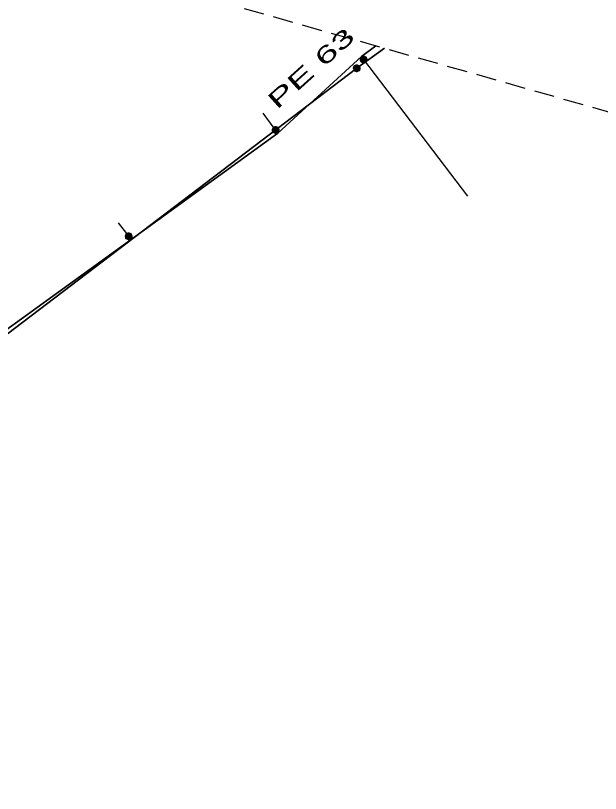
# Model space of a CAD drawing. Extents: x -873619 to -867639, y -1015082 to -1012326.
# Drawn here: x -868054.5 to -868016.1, y -1012689.5 to -1012638.4 of the extents above; entities that cross this region are included whole.
import ezdxf

# ---------------------------------------------------------------- set-up
doc = ezdxf.new("R2010")
doc.units = 0
doc.header["$LTSCALE"] = 0.44
doc.linetypes.add('MEDIUM_DASHED', pattern=[4.5, 3, -1.5])
for name, color, linetype, lineweight in [('1', 7, 'Continuous', 13), ('12', 7, 'Continuous', 13), ('21', 7, 'Continuous', 35), ('25', 7, 'Continuous', 13), ('3', 7, 'Continuous', 25), ('62', 7, 'MEDIUM_DASHED', 25)]:
    doc.layers.add(name, color=color, linetype=linetype, lineweight=lineweight)

msp = doc.modelspace()

# ---------------------------------------------------------------- linework, layer by layer
at = {"layer": '1', "lineweight": 35}
msp.add_lwpolyline([(-868030.886, -1012640.414), (-868031.841, -1012641.12), (-868037.319, -1012646.139), (-868046.957, -1012653.118), (-868059.317, -1012662.058), (-868070.578, -1012671.039), (-868077.42, -1012675.76), (-868086.156, -1012682.341)], dxfattribs=at)
at = {"layer": '12'}
for points in [[(-868031.458, -1012641.32), (-868031.465, -1012641.268), (-868031.482, -1012641.218), (-868031.511, -1012641.174), (-868031.548, -1012641.137), (-868031.593, -1012641.11), (-868031.642, -1012641.093), (-868031.696, -1012641.089), (-868031.747, -1012641.096), (-868031.796, -1012641.115), (-868031.84, -1012641.144), (-868031.875, -1012641.183), (-868031.902, -1012641.228), (-868031.918, -1012641.279), (-868031.921, -1012641.331), (-868031.913, -1012641.383), (-868031.892, -1012641.432), (-868031.862, -1012641.475), (-868031.823, -1012641.509), (-868031.777, -1012641.535), (-868031.725, -1012641.549), (-868031.673, -1012641.551), (-868031.622, -1012641.541), (-868031.573, -1012641.52), (-868031.531, -1012641.489), (-868031.497, -1012641.448), (-868031.473, -1012641.402), (-868031.46, -1012641.351)], [(-868031.489, -1012641.32), (-868031.495, -1012641.271), (-868031.512, -1012641.225), (-868031.539, -1012641.185), (-868031.576, -1012641.153), (-868031.62, -1012641.131), (-868031.669, -1012641.12), (-868031.718, -1012641.12), (-868031.764, -1012641.133), (-868031.808, -1012641.157), (-868031.843, -1012641.19), (-868031.87, -1012641.231), (-868031.887, -1012641.278), (-868031.891, -1012641.327), (-868031.884, -1012641.375), (-868031.865, -1012641.42), (-868031.835, -1012641.46), (-868031.796, -1012641.491), (-868031.752, -1012641.511), (-868031.705, -1012641.521), (-868031.656, -1012641.519), (-868031.608, -1012641.504), (-868031.566, -1012641.479), (-868031.531, -1012641.445), (-868031.505, -1012641.403), (-868031.492, -1012641.356)], [(-868031.519, -1012641.32), (-868031.524, -1012641.275), (-868031.541, -1012641.233), (-868031.57, -1012641.198), (-868031.605, -1012641.171), (-868031.647, -1012641.154), (-868031.693, -1012641.149), (-868031.737, -1012641.155), (-868031.779, -1012641.174), (-868031.813, -1012641.202), (-868031.84, -1012641.239), (-868031.857, -1012641.281), (-868031.86, -1012641.326), (-868031.853, -1012641.371), (-868031.835, -1012641.412), (-868031.806, -1012641.446), (-868031.769, -1012641.472), (-868031.725, -1012641.488), (-868031.681, -1012641.491), (-868031.636, -1012641.483), (-868031.595, -1012641.463), (-868031.561, -1012641.434), (-868031.536, -1012641.396), (-868031.522, -1012641.353)], [(-868031.549, -1012641.32), (-868031.553, -1012641.279), (-868031.571, -1012641.242), (-868031.598, -1012641.211), (-868031.634, -1012641.19), (-868031.674, -1012641.179), (-868031.715, -1012641.181), (-868031.754, -1012641.194), (-868031.788, -1012641.218), (-868031.813, -1012641.25), (-868031.828, -1012641.288), (-868031.83, -1012641.329), (-868031.823, -1012641.369), (-868031.803, -1012641.405), (-868031.774, -1012641.434), (-868031.737, -1012641.453), (-868031.696, -1012641.461), (-868031.656, -1012641.457), (-868031.617, -1012641.442), (-868031.585, -1012641.416), (-868031.563, -1012641.382), (-868031.549, -1012641.343)], [(-868031.578, -1012641.32), (-868031.583, -1012641.284), (-868031.602, -1012641.252), (-868031.627, -1012641.227), (-868031.661, -1012641.212), (-868031.698, -1012641.209), (-868031.732, -1012641.217), (-868031.764, -1012641.237), (-868031.786, -1012641.265), (-868031.799, -1012641.299), (-868031.799, -1012641.336), (-868031.789, -1012641.371), (-868031.767, -1012641.4), (-868031.737, -1012641.421), (-868031.703, -1012641.431), (-868031.666, -1012641.429), (-868031.632, -1012641.415), (-868031.605, -1012641.392), (-868031.585, -1012641.36), (-868031.578, -1012641.325)], [(-868031.608, -1012641.32), (-868031.614, -1012641.289), (-868031.63, -1012641.263), (-868031.656, -1012641.246), (-868031.686, -1012641.239), (-868031.718, -1012641.243), (-868031.745, -1012641.26), (-868031.762, -1012641.284), (-868031.771, -1012641.315), (-868031.767, -1012641.345), (-868031.752, -1012641.373), (-868031.727, -1012641.392), (-868031.698, -1012641.401), (-868031.666, -1012641.398), (-868031.639, -1012641.384), (-868031.619, -1012641.36), (-868031.608, -1012641.331)], [(-868031.639, -1012641.32), (-868031.644, -1012641.296), (-868031.661, -1012641.278), (-868031.683, -1012641.269), (-868031.708, -1012641.272), (-868031.728, -1012641.286), (-868031.74, -1012641.308), (-868031.74, -1012641.333), (-868031.727, -1012641.354), (-868031.708, -1012641.368), (-868031.683, -1012641.371), (-868031.659, -1012641.362), (-868031.644, -1012641.344)], [(-868031.669, -1012641.32), (-868031.674, -1012641.305), (-868031.688, -1012641.299), (-868031.703, -1012641.303), (-868031.71, -1012641.317), (-868031.706, -1012641.332), (-868031.693, -1012641.341), (-868031.678, -1012641.338), (-868031.669, -1012641.326)], [(-868037.238, -1012645.94), (-868037.244, -1012645.888), (-868037.261, -1012645.838), (-868037.29, -1012645.794), (-868037.327, -1012645.757), (-868037.372, -1012645.73), (-868037.422, -1012645.713), (-868037.475, -1012645.709), (-868037.527, -1012645.716), (-868037.576, -1012645.735), (-868037.619, -1012645.764), (-868037.655, -1012645.803), (-868037.681, -1012645.848), (-868037.697, -1012645.899), (-868037.7, -1012645.951), (-868037.692, -1012646.003), (-868037.672, -1012646.052), (-868037.641, -1012646.095), (-868037.602, -1012646.129), (-868037.556, -1012646.155), (-868037.505, -1012646.169), (-868037.452, -1012646.171), (-868037.401, -1012646.161), (-868037.353, -1012646.14), (-868037.31, -1012646.109), (-868037.276, -1012646.068), (-868037.252, -1012646.022), (-868037.24, -1012645.971)], [(-868037.268, -1012645.94), (-868037.274, -1012645.891), (-868037.291, -1012645.845), (-868037.319, -1012645.805), (-868037.356, -1012645.773), (-868037.4, -1012645.751), (-868037.448, -1012645.74), (-868037.497, -1012645.74), (-868037.544, -1012645.753), (-868037.587, -1012645.777), (-868037.623, -1012645.81), (-868037.65, -1012645.851), (-868037.666, -1012645.898), (-868037.67, -1012645.947), (-868037.663, -1012645.995), (-868037.644, -1012646.04), (-868037.614, -1012646.08), (-868037.576, -1012646.111), (-868037.532, -1012646.131), (-868037.484, -1012646.141), (-868037.435, -1012646.139), (-868037.388, -1012646.124), (-868037.345, -1012646.099), (-868037.311, -1012646.065), (-868037.285, -1012646.023), (-868037.271, -1012645.976)], [(-868037.298, -1012645.94), (-868037.304, -1012645.895), (-868037.321, -1012645.853), (-868037.349, -1012645.818), (-868037.385, -1012645.791), (-868037.427, -1012645.774), (-868037.472, -1012645.769), (-868037.517, -1012645.775), (-868037.558, -1012645.794), (-868037.593, -1012645.822), (-868037.62, -1012645.859), (-868037.636, -1012645.901), (-868037.64, -1012645.946), (-868037.633, -1012645.991), (-868037.614, -1012646.032), (-868037.585, -1012646.066), (-868037.548, -1012646.092), (-868037.505, -1012646.108), (-868037.46, -1012646.111), (-868037.415, -1012646.103), (-868037.375, -1012646.083), (-868037.341, -1012646.054), (-868037.315, -1012646.016), (-868037.301, -1012645.973)], [(-868037.328, -1012645.94), (-868037.333, -1012645.899), (-868037.351, -1012645.862), (-868037.378, -1012645.831), (-868037.413, -1012645.81), (-868037.453, -1012645.799), (-868037.494, -1012645.801), (-868037.533, -1012645.814), (-868037.567, -1012645.838), (-868037.592, -1012645.87), (-868037.607, -1012645.908), (-868037.61, -1012645.949), (-868037.602, -1012645.989), (-868037.582, -1012646.025), (-868037.553, -1012646.054), (-868037.516, -1012646.073), (-868037.476, -1012646.081), (-868037.435, -1012646.077), (-868037.397, -1012646.062), (-868037.365, -1012646.036), (-868037.342, -1012646.002), (-868037.329, -1012645.963)], [(-868037.358, -1012645.94), (-868037.363, -1012645.904), (-868037.381, -1012645.872), (-868037.407, -1012645.847), (-868037.441, -1012645.832), (-868037.477, -1012645.829), (-868037.512, -1012645.837), (-868037.543, -1012645.857), (-868037.566, -1012645.885), (-868037.579, -1012645.919), (-868037.579, -1012645.956), (-868037.568, -1012645.991), (-868037.547, -1012646.02), (-868037.517, -1012646.041), (-868037.482, -1012646.051), (-868037.445, -1012646.049), (-868037.411, -1012646.035), (-868037.384, -1012646.012), (-868037.365, -1012645.98), (-868037.358, -1012645.945)], [(-868037.388, -1012645.94), (-868037.393, -1012645.909), (-868037.41, -1012645.883), (-868037.436, -1012645.866), (-868037.466, -1012645.859), (-868037.497, -1012645.863), (-868037.524, -1012645.88), (-868037.542, -1012645.904), (-868037.55, -1012645.935), (-868037.546, -1012645.965), (-868037.531, -1012645.993), (-868037.507, -1012646.012), (-868037.477, -1012646.021), (-868037.446, -1012646.018), (-868037.418, -1012646.004), (-868037.398, -1012645.98), (-868037.388, -1012645.951)], [(-868037.418, -1012645.94), (-868037.423, -1012645.916), (-868037.44, -1012645.898), (-868037.463, -1012645.889), (-868037.487, -1012645.892), (-868037.508, -1012645.906), (-868037.519, -1012645.928), (-868037.519, -1012645.953), (-868037.507, -1012645.974), (-868037.487, -1012645.988), (-868037.462, -1012645.991), (-868037.439, -1012645.982), (-868037.423, -1012645.964)], [(-868037.448, -1012645.94), (-868037.453, -1012645.925), (-868037.468, -1012645.919), (-868037.483, -1012645.923), (-868037.49, -1012645.937), (-868037.486, -1012645.952), (-868037.473, -1012645.961), (-868037.458, -1012645.958), (-868037.448, -1012645.946)], [(-868046.878, -1012652.918), (-868046.884, -1012652.866), (-868046.901, -1012652.816), (-868046.93, -1012652.772), (-868046.967, -1012652.735), (-868047.012, -1012652.708), (-868047.062, -1012652.691), (-868047.115, -1012652.687), (-868047.167, -1012652.694), (-868047.216, -1012652.713), (-868047.259, -1012652.742), (-868047.295, -1012652.781), (-868047.321, -1012652.826), (-868047.337, -1012652.877), (-868047.34, -1012652.929), (-868047.332, -1012652.981), (-868047.312, -1012653.03), (-868047.281, -1012653.073), (-868047.242, -1012653.107), (-868047.196, -1012653.133), (-868047.145, -1012653.147), (-868047.092, -1012653.149), (-868047.041, -1012653.139), (-868046.993, -1012653.118), (-868046.95, -1012653.087), (-868046.916, -1012653.046), (-868046.892, -1012653), (-868046.88, -1012652.949)], [(-868046.908, -1012652.918), (-868046.914, -1012652.869), (-868046.931, -1012652.823), (-868046.959, -1012652.783), (-868046.996, -1012652.751), (-868047.04, -1012652.729), (-868047.088, -1012652.718), (-868047.137, -1012652.718), (-868047.184, -1012652.731), (-868047.227, -1012652.755), (-868047.263, -1012652.788), (-868047.29, -1012652.829), (-868047.306, -1012652.876), (-868047.31, -1012652.925), (-868047.303, -1012652.973), (-868047.284, -1012653.018), (-868047.254, -1012653.058), (-868047.216, -1012653.089), (-868047.172, -1012653.109), (-868047.124, -1012653.119), (-868047.075, -1012653.117), (-868047.028, -1012653.102), (-868046.985, -1012653.077), (-868046.951, -1012653.043), (-868046.925, -1012653.001), (-868046.911, -1012652.954)], [(-868046.938, -1012652.918), (-868046.944, -1012652.873), (-868046.961, -1012652.831), (-868046.989, -1012652.796), (-868047.025, -1012652.769), (-868047.067, -1012652.752), (-868047.112, -1012652.747), (-868047.157, -1012652.753), (-868047.198, -1012652.772), (-868047.233, -1012652.8), (-868047.26, -1012652.837), (-868047.276, -1012652.879), (-868047.28, -1012652.924), (-868047.273, -1012652.969), (-868047.254, -1012653.01), (-868047.225, -1012653.044), (-868047.188, -1012653.07), (-868047.145, -1012653.086), (-868047.1, -1012653.089), (-868047.055, -1012653.081), (-868047.015, -1012653.061), (-868046.981, -1012653.032), (-868046.955, -1012652.994), (-868046.941, -1012652.951)], [(-868046.968, -1012652.918), (-868046.973, -1012652.877), (-868046.991, -1012652.84), (-868047.018, -1012652.809), (-868047.053, -1012652.788), (-868047.093, -1012652.777), (-868047.134, -1012652.779), (-868047.173, -1012652.792), (-868047.207, -1012652.816), (-868047.232, -1012652.848), (-868047.247, -1012652.886), (-868047.25, -1012652.927), (-868047.242, -1012652.967), (-868047.222, -1012653.003), (-868047.193, -1012653.032), (-868047.156, -1012653.051), (-868047.116, -1012653.059), (-868047.075, -1012653.055), (-868047.037, -1012653.04), (-868047.005, -1012653.014), (-868046.982, -1012652.98), (-868046.969, -1012652.941)], [(-868046.998, -1012652.918), (-868047.003, -1012652.882), (-868047.021, -1012652.85), (-868047.047, -1012652.825), (-868047.081, -1012652.81), (-868047.117, -1012652.807), (-868047.152, -1012652.815), (-868047.183, -1012652.835), (-868047.206, -1012652.863), (-868047.219, -1012652.897), (-868047.219, -1012652.934), (-868047.208, -1012652.969), (-868047.187, -1012652.998), (-868047.157, -1012653.019), (-868047.122, -1012653.029), (-868047.085, -1012653.027), (-868047.051, -1012653.013), (-868047.024, -1012652.99), (-868047.005, -1012652.958), (-868046.998, -1012652.923)], [(-868047.028, -1012652.918), (-868047.033, -1012652.887), (-868047.05, -1012652.861), (-868047.076, -1012652.844), (-868047.106, -1012652.837), (-868047.137, -1012652.841), (-868047.164, -1012652.858), (-868047.182, -1012652.882), (-868047.19, -1012652.913), (-868047.186, -1012652.943), (-868047.171, -1012652.971), (-868047.147, -1012652.99), (-868047.117, -1012652.999), (-868047.086, -1012652.996), (-868047.058, -1012652.982), (-868047.038, -1012652.958), (-868047.028, -1012652.929)], [(-868047.058, -1012652.918), (-868047.063, -1012652.894), (-868047.08, -1012652.876), (-868047.103, -1012652.867), (-868047.127, -1012652.87), (-868047.148, -1012652.884), (-868047.159, -1012652.906), (-868047.159, -1012652.931), (-868047.147, -1012652.952), (-868047.127, -1012652.966), (-868047.102, -1012652.969), (-868047.079, -1012652.96), (-868047.063, -1012652.942)], [(-868047.088, -1012652.918), (-868047.093, -1012652.903), (-868047.108, -1012652.897), (-868047.123, -1012652.901), (-868047.13, -1012652.915), (-868047.126, -1012652.93), (-868047.113, -1012652.939), (-868047.098, -1012652.936), (-868047.088, -1012652.924)]]:
    msp.add_lwpolyline(points, close=True, dxfattribs=at)
at = {"layer": '21'}
msp.add_lwpolyline([(-868071.05, -1012671.53), (-868057.2, -1012660.92), (-868032.14, -1012641.89), (-868030.331, -1012640.572)], dxfattribs=at)
at = {"layer": '25'}
for points in [[(-868031.909, -1012641.89), (-868031.915, -1012641.838), (-868031.932, -1012641.788), (-868031.961, -1012641.744), (-868031.998, -1012641.707), (-868032.043, -1012641.68), (-868032.093, -1012641.663), (-868032.146, -1012641.659), (-868032.198, -1012641.666), (-868032.247, -1012641.685), (-868032.29, -1012641.714), (-868032.326, -1012641.753), (-868032.352, -1012641.798), (-868032.368, -1012641.849), (-868032.371, -1012641.901), (-868032.363, -1012641.953), (-868032.343, -1012642.002), (-868032.312, -1012642.045), (-868032.273, -1012642.079), (-868032.227, -1012642.105), (-868032.176, -1012642.119), (-868032.123, -1012642.121), (-868032.072, -1012642.111), (-868032.024, -1012642.09), (-868031.981, -1012642.059), (-868031.947, -1012642.018), (-868031.923, -1012641.972), (-868031.911, -1012641.921)], [(-868031.939, -1012641.89), (-868031.945, -1012641.841), (-868031.962, -1012641.795), (-868031.99, -1012641.755), (-868032.027, -1012641.723), (-868032.071, -1012641.701), (-868032.119, -1012641.69), (-868032.168, -1012641.69), (-868032.215, -1012641.703), (-868032.258, -1012641.727), (-868032.294, -1012641.76), (-868032.321, -1012641.801), (-868032.337, -1012641.848), (-868032.341, -1012641.897), (-868032.334, -1012641.945), (-868032.315, -1012641.99), (-868032.285, -1012642.03), (-868032.247, -1012642.061), (-868032.203, -1012642.081), (-868032.155, -1012642.091), (-868032.106, -1012642.089), (-868032.059, -1012642.074), (-868032.016, -1012642.049), (-868031.982, -1012642.015), (-868031.956, -1012641.973), (-868031.942, -1012641.926)], [(-868031.969, -1012641.89), (-868031.975, -1012641.845), (-868031.992, -1012641.803), (-868032.02, -1012641.768), (-868032.056, -1012641.741), (-868032.098, -1012641.724), (-868032.143, -1012641.719), (-868032.188, -1012641.725), (-868032.229, -1012641.744), (-868032.264, -1012641.772), (-868032.291, -1012641.809), (-868032.307, -1012641.851), (-868032.311, -1012641.896), (-868032.304, -1012641.941), (-868032.285, -1012641.982), (-868032.256, -1012642.016), (-868032.219, -1012642.042), (-868032.176, -1012642.058), (-868032.131, -1012642.061), (-868032.086, -1012642.053), (-868032.046, -1012642.033), (-868032.012, -1012642.004), (-868031.986, -1012641.966), (-868031.972, -1012641.923)], [(-868031.999, -1012641.89), (-868032.004, -1012641.849), (-868032.022, -1012641.812), (-868032.049, -1012641.781), (-868032.084, -1012641.76), (-868032.124, -1012641.749), (-868032.165, -1012641.751), (-868032.204, -1012641.764), (-868032.238, -1012641.788), (-868032.263, -1012641.82), (-868032.278, -1012641.858), (-868032.281, -1012641.899), (-868032.273, -1012641.939), (-868032.253, -1012641.975), (-868032.224, -1012642.004), (-868032.187, -1012642.023), (-868032.147, -1012642.031), (-868032.106, -1012642.027), (-868032.068, -1012642.012), (-868032.036, -1012641.986), (-868032.013, -1012641.952), (-868032, -1012641.913)], [(-868032.029, -1012641.89), (-868032.034, -1012641.854), (-868032.052, -1012641.822), (-868032.078, -1012641.797), (-868032.112, -1012641.782), (-868032.148, -1012641.779), (-868032.183, -1012641.787), (-868032.214, -1012641.807), (-868032.237, -1012641.835), (-868032.25, -1012641.869), (-868032.25, -1012641.906), (-868032.239, -1012641.941), (-868032.218, -1012641.97), (-868032.188, -1012641.991), (-868032.153, -1012642.001), (-868032.116, -1012641.999), (-868032.082, -1012641.985), (-868032.055, -1012641.962), (-868032.036, -1012641.93), (-868032.029, -1012641.895)], [(-868032.059, -1012641.89), (-868032.064, -1012641.859), (-868032.081, -1012641.833), (-868032.107, -1012641.816), (-868032.137, -1012641.809), (-868032.168, -1012641.813), (-868032.195, -1012641.83), (-868032.213, -1012641.854), (-868032.221, -1012641.885), (-868032.217, -1012641.915), (-868032.202, -1012641.943), (-868032.178, -1012641.962), (-868032.148, -1012641.971), (-868032.117, -1012641.968), (-868032.089, -1012641.954), (-868032.069, -1012641.93), (-868032.059, -1012641.901)], [(-868032.089, -1012641.89), (-868032.094, -1012641.866), (-868032.111, -1012641.848), (-868032.134, -1012641.839), (-868032.158, -1012641.842), (-868032.179, -1012641.856), (-868032.19, -1012641.878), (-868032.19, -1012641.903), (-868032.178, -1012641.924), (-868032.158, -1012641.938), (-868032.133, -1012641.941), (-868032.11, -1012641.932), (-868032.094, -1012641.914)], [(-868032.119, -1012641.89), (-868032.124, -1012641.875), (-868032.139, -1012641.869), (-868032.154, -1012641.873), (-868032.161, -1012641.887), (-868032.157, -1012641.902), (-868032.144, -1012641.911), (-868032.129, -1012641.908), (-868032.119, -1012641.896)]]:
    msp.add_lwpolyline(points, close=True, dxfattribs=at)
at = {"layer": '3'}
msp.add_line((-868037.319, -1012646.139), (-868038.296, -1012644.841), dxfattribs=at)
for points in [[(-868031.841, -1012641.12), (-868031.69, -1012641.32), (-868024.876, -1012650.288)], [(-868047.795, -1012652.025), (-868047.11, -1012652.92), (-868046.957, -1012653.118)]]:
    msp.add_lwpolyline(points, dxfattribs=at)
at = {"layer": '62'}
msp.add_lwpolyline([(-873556.163, -1013770.63), (-872990.942, -1013058.87), (-872369.897, -1012591.341), (-871448.796, -1012465.737), (-870583.52, -1012702.99), (-868999.506, -1012326.176), (-868524.999, -1012528.539), (-868252.856, -1012577.385), (-867687.635, -1012737.88), (-867638.789, -1013044.914), (-867827.196, -1013184.475), (-868176.097, -1013763.652), (-868434.285, -1014335.85), (-868650.604, -1014635.906), (-869550.77, -1014963.874), (-870206.706, -1015082.5), (-871092.916, -1015026.676), (-871923.303, -1014566.126), (-872607.15, -1014370.741), (-872865.338, -1014447.499), (-873284.02, -1014259.092), (-873402.646, -1014252.114), (-873618.965, -1014280.026)], close=True, dxfattribs=at)

# ---------------------------------------------------------------- texts
at = {"layer": '1', "width": 1.75}
msp.add_text('PE 63 ', height=1.1, rotation=42, dxfattribs=at).set_placement((-868037.384, -1012644.639))

doc.saveas('drawing.dxf')
